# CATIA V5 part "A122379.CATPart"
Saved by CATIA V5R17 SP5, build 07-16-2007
Part number: MS25036-149
Revision: -
Definition: A122379
Nomenclature: TERMINAL, LUG, CRIMP STYLE, COPPER, INSULATED, RING TONGUE,
Source: bought
Description: TERMINAL, LUG, CRIMP STYLE, COPPER, INSULATED, RING TONGUE, BELL-MOUTHED, TYPE II, CLASS 1, (FOR 105 DEG. C TOTAL CONDUCTOR TEMPERATURE)
Publications: "Logical Termination.1", "Logical Pin.1", "BCP", "Point.4_generated(BCP)", "Face_generated(BCP)", "CaCP", "Face_generated(CaCP)", "Line.1_generated(CaCP)", "Face_generated(BCP).1"
Material "Density=.0980": density 2712.63 kg/m3
Bounding box of the stored display mesh (mm): x -4.064 to 19.558, y -4.016 to 4.016, z -1.425 to 5.565
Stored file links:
  C:\Users\u305772\OneDrive - Gulfstream Aerospace\AD PAG\Harness\A122379.CATPart
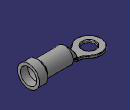
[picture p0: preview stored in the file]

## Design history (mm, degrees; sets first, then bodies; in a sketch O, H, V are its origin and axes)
Parameters
  PartNumber = "MS25036-149"
  OtherKeywords = "TERMINAL, LUG, CRIMP STYLE, COPPER, INSULATED, RING TONGUE, BELL-MOUTHED, TYPE II, CLASS 1, (FOR 105 DEG. C TOTAL CONDUCTOR TEMPERATURE)"
  Comments = ""
  CAGECode = "81343"
  WeightComment = "CALCULATED BY CATIA"
  WeightSource = "Calculated"
  Density = 2712.17 (density)
  Volume = 2.90891e-07 (volume) {= smartVolume(Body1)}
  Ring_OD = 8.128 mm
  Ring_ID = 4.2672 mm
  Length = 23.622 mm
  Ring_Thickness = 0.889 mm
  Bell_Mouth_OD = 7.112 mm
  Length_to_Crimp_Shaft = 5.1308 mm
  Bell_Mouth_Length = 3.175 mm
  Crimp_Shaft_ID = 1.8542 mm
  Insulation_Crimp_Shaft_OD = 5.461 mm
  Insulation_Length = 8.9916 mm
  Crimp_Shaft_OD = 3.6322 mm
  Weight = 0.0017637
Set1
  Plane1: type Offset, RefPlane xy-plane, Offset 2.0701 {= Crimp_Shaft_OD/2+.01in}
  Point1: (0, 0, 0)
  Point2: (0, 0, 2.54), relative to Point1
  Point3: (16.383 {= Length-(Ring_OD /2)-Bell_Mouth_Length}, 0, 1.8161 {= Crimp_Shaft_OD/2})
  Line1: type PtPt, FirstPoint Point1, SecondPoint Point2
Body1 (main body)
  Sketch1 on Plane1, origin (0, 0, 2.0701), H (0, 1, 0), V (-1, 0, 0)
    point P1 (1.8161, -16.383)
    line L1 (1.8161, -16.383) -> (2.6416, -17.2085)
    line L2 (2.6416, -17.2085) -> (2.6416, -19.558)
    line L3 (2.6416, -19.558) -> (3.556, -19.558)
    line L4 (3.556, -19.558) -> (3.556, -16.8297)
    point P5 (3.556, -16.8297)
    line L5 (3.556, -16.8297) -> (2.7305, -16.0042)
    line L6 (2.7305, -16.0042) -> (2.7305, -7.8381)
    line L7 (1.8161, -5.1308) -> (0.9271, -5.1308)
    point P7 (1.8161, -16.383)
    line L8 (1.8161, -16.383) -> (0.9271, -16.383)
    point P8 (0.9271, -16.383)
    line L9 (0.9271, -16.383) -> (0.9271, -5.1308)
    line L10 (2.7305, -7.8381) -> (1.8161, -7.8381)
    line L11 (1.8161, -7.8381) -> (1.8161, -5.1308)
    angle L2 L1 = 45
    distance L4 V = 3.556 {= Bell_Mouth_OD/2}
    distance L2 L4 = 0.9144 {= (Insulation_Crimp_Shaft_OD -Crimp_Shaft_OD )/2}
    distance L9 V = 0.9271 {= Crimp_Shaft_ID/2}
    distance L6 V = 2.7305 {= Insulation_Crimp_Shaft_OD/2}
    distance L3 H = 19.558 {= Length-(Ring_OD /2)}
    distance L8 L3 = 3.175 {= Bell_Mouth_Length}
    distance P1 P8 H = 0.889 {= Ring_Thickness}
    distance L5 L1 = 0.9144 {= Sketch1.distance(L2 L4)}
    distance H L7 = 5.1308 {= Length_to_Crimp_Shaft}
    distance L11 L9 = 0.889 {= Sketch1.distance(P1 P8 H)}
    distance P5 L10 = 8.9916 {= Insulation_Length}
    vertical: L2 V, L4 V, L6 V, L9 V, L11 V
    horizontal: L3 H, L7 H, L8 H, L10 H
    coincidence: P1 P7
  Shaft1: profile Sketch1, axis Sketch1.V, angle 360
  Sketch2 on xy-plane, origin (0, 0, 0), H (0, 1, 0), V (-1, 0, 0)
    arc A1 centre (0, 0) radius 4.064 from (2.8571, -2.8902) to (-2.8571, -2.8902) ccw
    point P1 (0, 0)
    arc A2 centre (-5.3213, -5.383) radius 3.5052 from (-2.8571, -2.8902) to (-1.8161, -5.383) cw
    point P2 (-5.3213, -5.383)
    line L1 (-1.8161, -5.383) -> (-1.8161, -6.0198)
    line L2 (1.8161, -6.0198) -> (1.8161, -5.383)
    arc A3 centre (5.3213, -5.383) radius 3.5052 from (1.8161, -5.383) to (2.8571, -2.8902) cw
    point P5 (5.3213, -5.383)
    line L3 (1.8161, -6.0198) -> (-1.8161, -6.0198)
    radius A1 = 4.064 {= Ring_OD /2}
    radius A2 = 3.5052 {= Ring_ID -.03in}
    radius A3 = 3.5052 {= Sketch2.radius(A2)}
    distance P5 P2 V = 0
    distance L3 H = 6.0198 {= Length_to_Crimp_Shaft +.035in}
    distance L2 V = 1.8161 {= (Crimp_Shaft_ID /2)+Ring_Thickness}
    coincidence: P1 O
    tangency: L1 A2, A3 L2, A3 A1, A2 A1
    horizontal: L3 H
    vertical: L2 V, L1 V
  Pad1: profile Sketch2, direction (0, 0, 1), length 0.889 {= Ring_Thickness}
  Sketch3 on end face of Pad1, origin (0.6377, -0.4749, 0.889), H (1, 0, 0), V (0, 1, 0)
    point P1 (-0.6377, 0.4749)
    reference projected arc E1 centre (-0.6377, 0.4749) radius 4.064 from (2.4584, 3.1075) to (2.4584, -2.1577) ccw from edge [face of Pad1 from Sketch2.A1 | end face of Pad1]
    concentricity: P1 E1
  Hole1: placed by Sketch3, at (0, 0, 0.889) direction (0, 0, -1), diameter 4.2672 {= Ring_ID}, through (limit type 3)
  Chamfer1: length 0.635 {= Ring_Thickness-.01in}, angle 45, on edge [face of Shaft1 from Sketch1.L9 | face of Shaft1 from Sketch1.L8]
  Sketch4 on zx-plane, origin (0, 0, 0), H (-1, 0, 0), V (0, 0, 1)
    line L1 (-5.1308, 0.889) -> (-8.2903, 6.3614)
    point P1 (-5.1308, 0.889)
    line L2 (-5.1308, 7.0007) -> (-5.1308, 0.889)
    reference projected point E1 (-5.1308, 0.889) from edge [face of Shaft1 from Sketch1.L7 | end face of Pad1]
    projected line E2 (-5.1308, 3.8862) -> (-5.1308, 0.889) from edge [face of Shaft1 from Sketch1.L11 | face of Shaft1 from Sketch1.L7]
    line L3 (-8.2903, 6.3614) -> (-5.1308, 7.0007)
    angle L1 L2 = 30
    angle L3 L2 = 78.5616
    length L2 = 6.1117
    coincidence: P1 E1, L2 E2
  Pocket1: profile Sketch4, direction (0, -1, 0), length 25.4, opposite side length 25.4
  Fillet1: radius 0.381, on edge [face of Pad1 from Sketch2.L2 | face of Pad1 from Sketch2.L3]; edge [face of Pad1 from Sketch2.L3 | face of Pad1 from Sketch2.L1]
  Fillet2: radius 0.1651, on face of Pad1 from Sketch2.A3; face of Hole1
  Fillet3: radius 0.1651, on face of Pocket1 from Sketch4.L1; edge [face of Shaft1 from Sketch1.L11 | end face of Pad1]; edge [end face of Pad1 | face of Shaft1 from Sketch1.L11]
